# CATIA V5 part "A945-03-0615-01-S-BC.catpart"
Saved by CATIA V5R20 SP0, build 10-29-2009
Part number: A945-03-0615-01-S-BC
Source: Unknown
Property "ARTICLENO": "A945-03-0615-01-S-BC"
Property "B": "65.000"
Property "BOMINFO": "A945-03-0615-01-S-BC"
Property "CODE": "A945-03-0615-01-S-BC"
Property "D1": "20.000"
Property "D2": "13.500"
Property "D5": "16.000"
Property "D6": "12.000"
Property "H": "47.000"
Property "H1": "34.000"
Property "H2": "35.000"
Property "H3": "18.000"
Property "L1": "150.000"
Property "L2": "25.000"
Property "L3": "0.000"
Property "L4": "100.000"
Property "L5": "55.000"
Property "L6": "45.000"
Property "LINA": "A945-03-0615-01-S-BC"
Property "N": "1.000"
Property "NB": "A945-03-0615-01-S-BC"
Property "NBSYN": "$CODE."
Property "NN": "A945-03"
Property "NT": "v driver sets replaceable inserts pisitive return"
Property "SUPPLIER": "CF"
Property "Z": "65.000"
Bounding box of the stored display mesh (mm): x -5049.207 to -4951.207, y -575.36 to -510.36, z 0 to 150
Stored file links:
  C:\Users\Utente\Desktop\3D files A945-03\A945-03-0615-01-S-BC.catpart
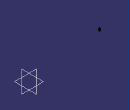
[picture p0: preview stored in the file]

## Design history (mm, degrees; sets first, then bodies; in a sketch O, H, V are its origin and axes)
Body1 "Geometry.1" (main body)
  Solid1 "A945-03-0615-01-S-BC.catpart": solid without history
